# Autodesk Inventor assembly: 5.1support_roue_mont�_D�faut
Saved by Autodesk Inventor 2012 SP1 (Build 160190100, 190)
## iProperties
Created: 2011-01
Part Number: 5.1support_roue_mont�_D�faut
Document SubType Name: Assembly
Designer: eric
Mass: 34.9166 g
Surface Area: 331.186 cm^2
Volume: 34.9166 cm^3
Density: 1 g/cm^3
Author: eric
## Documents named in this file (7)
- D:\Cours\Inventor salle SI\chariot_de_golf_2008\chariot_de_golf_trolem\5.1support_roue_monte_Defaut.iam
- D:\Cours\Inventor salle SI\chariot_de_golf_2008\chariot_de_golf_trolem\5.1tube_roulement_Defaut.ipt
- D:\Cours\Inventor salle SI\chariot_de_golf_2008\chariot_de_golf_trolem\5.1roulement_12x28x8_Defaut.iam
- D:\Cours\Inventor salle SI\chariot_de_golf_2008\chariot_de_golf_trolem\5.1support roulement_Defaut.ipt
- D:\Cours\Inventor salle SI\chariot_de_golf_2008\chariot_de_golf_trolem\bead102_Defaut.ipt
- D:\Cours\Inventor salle SI\chariot_de_golf_2008\chariot_de_golf_trolem\bead101_Defaut.ipt
- D:\Cours\Inventor salle SI\chariot_de_golf_2008\chariot_de_golf_trolem\bead100_Defaut.ipt
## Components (7 placed, 6 different names)
1. 5.1tube_roulement_Defaut:1
2. 5.1roulement_12x28x8_Defaut:1 [sub-assembly]
3. 5.1support roulement_Defaut:1
4. bead102_Defaut:1
5. bead101_Defaut:1
6. bead100_Defaut:1
7. 5.1roulement_12x28x8_Defaut:2 [sub-assembly]
